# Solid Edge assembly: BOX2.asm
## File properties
Author: Andrea Rangi V
Template: Ansi Metric assembly.asm
Last saved by: Andrea Rangi V
Revision: 2
Application: Solid Edge
Username: Andrea Rangi V
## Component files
TOP2.par
BACK2.par
SIDES2.par
HAT2.par
FRONT2.par
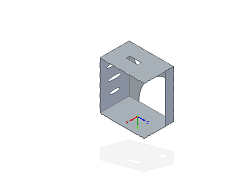
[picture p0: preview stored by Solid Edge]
